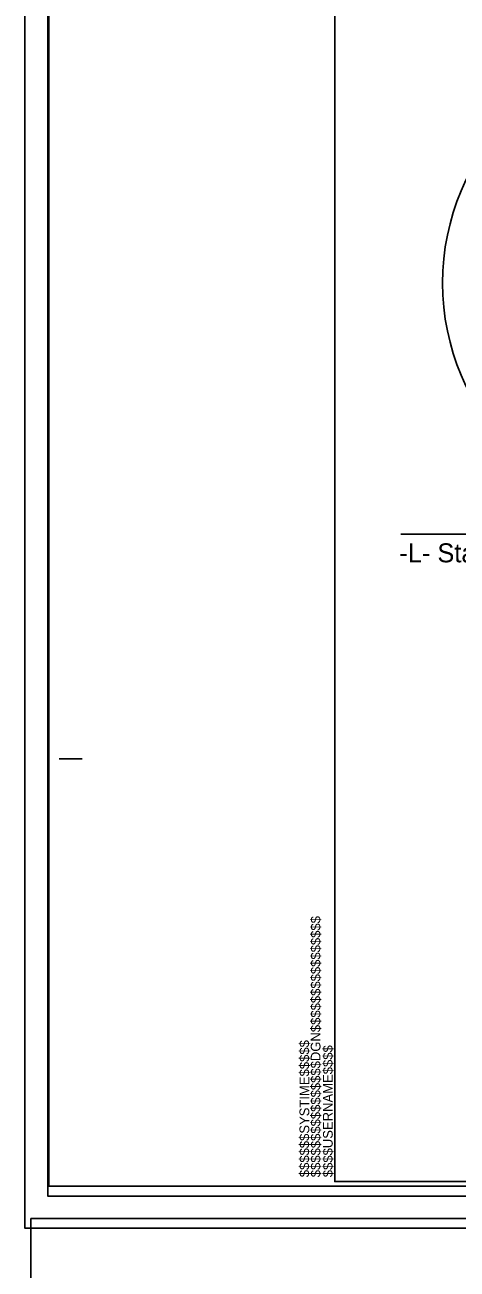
# Model space of a CAD drawing. Extents: x 2294455 to 2294795, y 719276 to 719941.
# Drawn here: x 2294454.5 to 2294501.1, y 719490.9 to 719624.9 of the extents above; entities that cross this region are included whole.
import ezdxf

# ---------------------------------------------------------------- set-up
doc = ezdxf.new("R2010")
doc.units = 0
for name, color, linetype in [('Default', 7, 'Continuous'), ('Old_Level_1', 7, 'Continuous'), ('Old_Level_11', 7, 'Continuous'), ('Sheet Cutting Line CELL', 7, 'Continuous'), ('Sheet Plot Border Inside CELL', 7, 'Continuous'), ('Sheet Plot Border Outside CELL', 7, 'Continuous'), ('Sheet Typical CELL', 7, 'Continuous')]:
    doc.layers.add(name, color=color, linetype=linetype)

msp = doc.modelspace()

# ---------------------------------------------------------------- linework, layer by layer
at = {"layer": 'Default'}
msp.add_lwpolyline([(2294454.52, 719715.33), (2294794.52, 719715.33), (2294794.52, 719495.33), (2294454.52, 719495.33)], close=True, dxfattribs=at)
at = {"layer": 'Old_Level_11'}
msp.add_line((2294495.06, 719570.03), (2294556.58, 719570.03), dxfattribs=at)
msp.add_circle((2294525.06, 719597.06), 25.51, dxfattribs=at)
at = {"layer": 'Sheet Cutting Line CELL'}
for p, q in [((2294791.96, 719496.34), (2294455.16, 719496.34)), ((2294455.16, 719496.34), (2294455.16, 719276.34))]:
    msp.add_line(p, q, dxfattribs=at)
at = {"layer": 'Sheet Plot Border Inside CELL'}
msp.add_lwpolyline([(2294790.42, 719710.84), (2294457.12, 719710.84), (2294457.12, 719499.82), (2294790.42, 719499.82)], close=True, dxfattribs=at)
at = {"layer": 'Sheet Plot Border Outside CELL'}
for points in [[(2294793.79, 719718.76), (2294456.99, 719718.76), (2294456.99, 719498.76), (2294793.79, 719498.76)], [(2294794.52, 719715.33), (2294454.52, 719715.33), (2294454.52, 719495.33), (2294794.52, 719495.33)]]:
    msp.add_lwpolyline(points, close=True, dxfattribs=at)
at = {"layer": 'Sheet Typical CELL'}
for p, q in [((2294458.22, 719545.83), (2294460.72, 719545.83)), ((2294487.92, 719500.33), (2294487.92, 719500.33)), ((2294487.92, 719500.33), (2294487.92, 719500.33)), ((2294487.92, 719500.33), (2294487.92, 719500.33)), ((2294487.92, 719500.33), (2294487.92, 719500.33)), ((2294487.92, 719500.33), (2294487.92, 719500.33)), ((2294487.92, 719500.33), (2294487.92, 719500.33))]:
    msp.add_line(p, q, dxfattribs=at)
msp.add_lwpolyline([(2294787.92, 719710.33), (2294487.92, 719710.33), (2294487.92, 719500.33), (2294787.92, 719500.33)], close=True, dxfattribs=at)
msp.add_lwpolyline([(2294495.42, 719500.33), (2294495.42, 719500.33)], dxfattribs=at)

# ---------------------------------------------------------------- texts
at = {"layer": 'Old_Level_1'}
msp.add_text('-L- Sta. 617+51.26 LT to Sta. 621+41.31 LT', height=2.0454, rotation=0, dxfattribs=at).set_placement((2294494.89, 719566.99))
at = {"layer": 'Sheet Typical CELL'}
for s, p in [('$$$$$$$$$$$$$$$$DGN$$$$$$$$$$$$$$$$', (2294486.39, 719500.8)), ('$$$$$$SYSTIME$$$$$', (2294485.18, 719500.8)), ('$$$$USERNAME$$$$', (2294487.71, 719500.8))]:
    msp.add_text(s, height=1.05, rotation=90, dxfattribs=at).set_placement(p)

doc.saveas('drawing.dxf')
